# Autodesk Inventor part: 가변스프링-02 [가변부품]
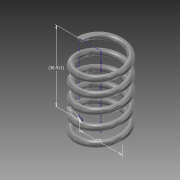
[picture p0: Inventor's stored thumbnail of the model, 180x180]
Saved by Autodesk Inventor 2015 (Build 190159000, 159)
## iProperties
Created: 2014-12
Part Number: 가변스프링-02 [가변부품]
Material: Steel, Carbon
Document SubType Name: Modeling
Designer: Deny
Density: 7.85 g/cm^3
Appearance: Semi-Polished
Mass: 18.8395 g
Surface Area: 32.544 cm^2
Volume: 2.39994 cm^3
Author: Deny
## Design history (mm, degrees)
sketch "Sketch1"
  geometry: L1 (0, 0)-(11, 0); L2 (11, 0)-(11, 36.411); L3 (11, 36.411)-(0, 36.411); L4 (0, 36.411)-(0, 0); C1 r 1.5 at (11, 0)
  constraints: 8 end point, 2 parallel, 1 centre point, 1 coincident, 1 horizontal, 1 perpendicular
  dimensions: "d0" = 3 diameter of C1; "d1" = 22 diameter of L2 L4; "d2" = 36.4112 distance between parallel lines of L1 L3 (derived)
coil "Coil1" sketch "Sketch1" pitch "d3" = 10; turns "d5" = 5; dims "d4" = 36.4112 (= d2), "d6" = 0, angle "d7" = 90 deg, angle "d8" = 90 deg, "d9" = 0, "d10" = 0
sketch "Sketch2"
  geometry: L1 (-12.5, 0)-(-9.5, 0) reference; 1 further point
  constraints: 1 horizontal alignment
extrude "Extrusion1" cut sketch "Sketch2" stored distance "d11" = 10; taper "d12" = 0 deg
workplane "Work Plane1"
sketch "Sketch3"
  geometry: L1 (1.5, 0)-(-1.5, 0) reference; 1 further point
  constraints: 1 horizontal alignment
extrude "Extrusion2" cut sketch "Sketch3" stored distance "d14" = 10; taper "d15" = 0 deg
body "Solid1"
node "Project Cut Edges1"
node "Project Cut Edges2"
other parameters: "d13" = 0
